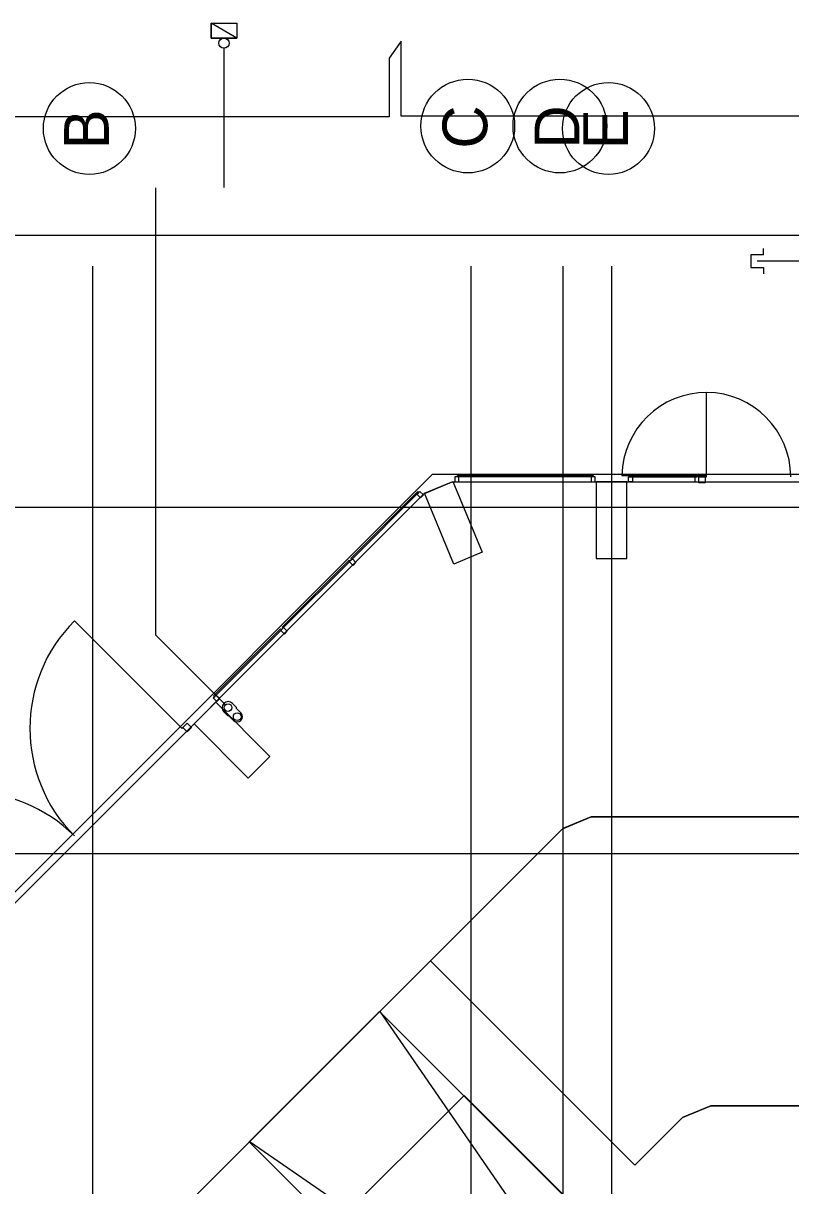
# Model space of a CAD drawing. Extents: x -264222 to -263592, y -1242345 to -1242048.
# Drawn here: x -263902.97 to -263887.96, y -1242101.22 to -1242078.49 of the extents above; entities that cross this region are included whole.
import ezdxf

# ---------------------------------------------------------------- set-up
doc = ezdxf.new("R2010")
doc.units = 0
for name, color, linetype in [('HESCON_OSI_STAVBY_KFA', 7, 'Continuous'), ('KFA_2D_SITUACIA_DSP', 7, 'Continuous'), ('KFA_SO_62-1_VO_TRASA_KABLOV_PROJEKT', 7, 'Continuous')]:
    doc.layers.add(name, color=color, linetype=linetype)

msp = doc.modelspace()

# ---------------------------------------------------------------- linework, layer by layer
at = {"layer": 'HESCON_OSI_STAVBY_KFA'}
for p, q in [((-263901.618, -1242083.237), (-263901.618, -1242083.237)), ((-263901.618, -1242083.237), (-263901.618, -1242246.707)), ((-263894.218, -1242083.237), (-263894.218, -1242083.237)), ((-263894.218, -1242083.237), (-263894.218, -1242246.707)), ((-263892.418, -1242083.237), (-263892.418, -1242083.237)), ((-263892.418, -1242083.237), (-263892.418, -1242246.707)), ((-263891.468, -1242083.237), (-263891.468, -1242083.237)), ((-263891.468, -1242083.237), (-263891.468, -1242246.707)), ((-263792.653, -1242087.957), (-263911.523, -1242087.957)), ((-263792.653, -1242094.732), (-263911.523, -1242094.732))]:
    msp.add_line(p, q, dxfattribs=at)
for centre, radius in [((-263901.678, -1242080.545), 0.899), ((-263894.278, -1242080.498), 0.916), ((-263892.478, -1242080.498), 0.916), ((-263891.528, -1242080.545), 0.899)]:
    msp.add_circle(centre, radius, dxfattribs=at)
at = {"layer": 'KFA_2D_SITUACIA_DSP'}
for p, q in [((-263899.296, -1242078.777), (-263899.296, -1242078.487)), ((-263899.296, -1242078.487), (-263898.796, -1242078.487)), ((-263898.796, -1242078.777), (-263899.296, -1242078.487)), ((-263898.796, -1242078.777), (-263899.296, -1242078.487)), ((-263899.296, -1242078.487), (-263899.296, -1242078.777)), ((-263898.796, -1242078.487), (-263898.796, -1242078.777)), ((-263898.796, -1242078.777), (-263899.296, -1242078.777)), ((-263899.296, -1242078.777), (-263898.796, -1242078.777)), ((-263899.046, -1242078.977), (-263899.047, -1242081.696)), ((-263900.379, -1242090.456), (-263900.379, -1242081.705)), ((-263788.143, -1242082.64), (-263924.143, -1242082.64)), ((-263888.493, -1242083.015), (-263888.743, -1242083.015)), ((-263888.743, -1242083.015), (-263888.743, -1242083.265)), ((-263888.493, -1242083.015), (-263888.493, -1242082.89)), ((-263888.743, -1242083.265), (-263888.493, -1242083.265)), ((-263886.743, -1242083.14), (-263888.618, -1242083.14)), ((-263888.493, -1242083.265), (-263888.493, -1242083.39)), ((-263889.613, -1242087.357), (-263889.613, -1242085.707)), ((-263894.491, -1242087.357), (-263894.531, -1242087.357)), ((-263894.531, -1242087.357), (-263894.531, -1242087.457)), ((-263894.451, -1242087.357), (-263894.491, -1242087.357)), ((-263894.478, -1242087.332), (-263891.828, -1242087.332)), ((-263894.478, -1242087.357), (-263894.478, -1242087.332)), ((-263891.828, -1242087.357), (-263894.478, -1242087.357)), ((-263894.451, -1242087.457), (-263894.451, -1242087.357)), ((-263891.828, -1242087.357), (-263891.868, -1242087.357)), ((-263891.868, -1242087.357), (-263891.868, -1242087.457)), ((-263891.828, -1242087.332), (-263891.828, -1242087.357)), ((-263891.788, -1242087.357), (-263891.828, -1242087.357)), ((-263891.788, -1242087.457), (-263891.788, -1242087.357)), ((-263891.263, -1242087.332), (-263889.613, -1242087.332)), ((-263891.138, -1242087.457), (-263891.138, -1242087.357)), ((-263891.138, -1242087.357), (-263891.098, -1242087.357)), ((-263889.798, -1242087.332), (-263891.098, -1242087.332)), ((-263891.098, -1242087.332), (-263891.098, -1242087.357)), ((-263891.098, -1242087.357), (-263889.798, -1242087.357)), ((-263891.098, -1242087.357), (-263891.058, -1242087.357)), ((-263891.058, -1242087.357), (-263891.058, -1242087.457)), ((-263889.798, -1242087.357), (-263889.838, -1242087.357)), ((-263889.838, -1242087.357), (-263889.838, -1242087.457)), ((-263889.798, -1242087.357), (-263889.798, -1242087.332)), ((-263889.758, -1242087.357), (-263889.798, -1242087.357)), ((-263889.758, -1242087.457), (-263889.758, -1242087.357)), ((-263889.758, -1242087.477), (-263889.758, -1242087.357)), ((-263889.758, -1242087.357), (-263889.638, -1242087.357)), ((-263889.638, -1242087.357), (-263889.613, -1242087.357)), ((-263889.638, -1242087.357), (-263889.638, -1242087.477)), ((-263895.258, -1242087.647), (-263896.566, -1242088.955)), ((-263895.24, -1242087.665), (-263895.258, -1242087.647)), ((-263895.245, -1242087.67), (-263895.216, -1242087.641)), ((-263895.216, -1242087.641), (-263895.146, -1242087.712)), ((-263895.135, -1242087.687), (-263894.581, -1242087.457)), ((-263895.125, -1242087.676), (-263894.571, -1242087.447)), ((-263894.581, -1242087.457), (-263809.355, -1242087.457)), ((-263894.571, -1242087.447), (-263893.997, -1242088.832)), ((-263894.531, -1242087.457), (-263894.451, -1242087.457)), ((-263891.868, -1242087.457), (-263891.788, -1242087.457)), ((-263891.168, -1242087.452), (-263891.768, -1242087.452)), ((-263891.768, -1242087.452), (-263891.768, -1242088.952)), ((-263891.168, -1242088.952), (-263891.168, -1242087.452)), ((-263891.058, -1242087.457), (-263891.138, -1242087.457)), ((-263889.838, -1242087.457), (-263889.758, -1242087.457)), ((-263889.638, -1242087.477), (-263889.758, -1242087.477)), ((-263908.663, -1242101.215), (-263895.135, -1242087.687)), ((-263896.548, -1242088.973), (-263895.24, -1242087.665)), ((-263895.273, -1242087.698), (-263895.245, -1242087.67)), ((-263895.202, -1242087.769), (-263895.273, -1242087.698)), ((-263895.146, -1242087.712), (-263895.202, -1242087.769)), ((-263894.551, -1242089.062), (-263895.125, -1242087.676)), ((-263897.906, -1242090.295), (-263896.598, -1242088.987)), ((-263896.58, -1242089.005), (-263897.888, -1242090.313)), ((-263896.598, -1242088.987), (-263896.58, -1242089.005)), ((-263896.592, -1242089.017), (-263896.564, -1242088.989)), ((-263896.566, -1242088.955), (-263896.548, -1242088.973)), ((-263896.564, -1242088.989), (-263896.536, -1242088.96)), ((-263896.536, -1242088.96), (-263896.465, -1242089.031)), ((-263893.997, -1242088.832), (-263894.551, -1242089.062)), ((-263891.768, -1242088.952), (-263891.168, -1242088.952)), ((-263896.522, -1242089.088), (-263896.592, -1242089.017)), ((-263896.465, -1242089.031), (-263896.522, -1242089.088)), ((-263899.866, -1242092.276), (-263901.97, -1242090.173)), ((-263899.25, -1242091.639), (-263897.942, -1242090.331)), ((-263897.924, -1242090.349), (-263899.232, -1242091.657)), ((-263897.942, -1242090.331), (-263897.924, -1242090.349)), ((-263897.936, -1242090.361), (-263897.908, -1242090.333)), ((-263897.865, -1242090.432), (-263897.936, -1242090.361)), ((-263897.908, -1242090.333), (-263897.88, -1242090.304)), ((-263897.888, -1242090.313), (-263897.906, -1242090.295)), ((-263897.88, -1242090.304), (-263897.809, -1242090.375)), ((-263897.809, -1242090.375), (-263897.865, -1242090.432)), ((-263899.018, -1242091.817), (-263900.379, -1242090.456)), ((-263899.255, -1242091.68), (-263899.227, -1242091.652)), ((-263899.185, -1242091.751), (-263899.255, -1242091.68)), ((-263899.232, -1242091.657), (-263899.25, -1242091.639)), ((-263899.227, -1242091.652), (-263899.199, -1242091.624)), ((-263899.199, -1242091.624), (-263899.128, -1242091.694)), ((-263899.128, -1242091.694), (-263899.185, -1242091.751)), ((-263899.207, -1242091.764), (-263899.631, -1242092.188)), ((-263898.147, -1242092.824), (-263899.207, -1242091.764)), ((-263898.969, -1242092.031), (-263899.047, -1242091.953)), ((-263899.047, -1242091.953), (-263898.969, -1242092.031)), ((-263898.804, -1242091.866), (-263898.882, -1242091.787)), ((-263898.804, -1242091.885), (-263898.804, -1242091.866)), ((-263898.715, -1242091.974), (-263898.804, -1242091.885)), ((-263899.764, -1242092.174), (-263899.849, -1242092.259)), ((-263899.679, -1242092.259), (-263899.764, -1242092.174)), ((-263899.631, -1242092.188), (-263898.571, -1242093.249)), ((-263898.949, -1242092.031), (-263898.969, -1242092.031)), ((-263898.861, -1242092.119), (-263898.949, -1242092.031)), ((-263899.849, -1242092.259), (-263899.866, -1242092.276)), ((-263899.849, -1242092.259), (-263899.764, -1242092.344)), ((-263899.764, -1242092.344), (-263899.679, -1242092.259)), ((-263898.571, -1242093.249), (-263898.147, -1242092.824)), ((-263891.868, -1242094.007), (-263892.422, -1242094.237)), ((-263874.98, -1242094.007), (-263891.868, -1242094.007)), ((-263892.422, -1242094.237), (-263895.005, -1242096.82)), ((-263895.005, -1242096.82), (-263891.01, -1242100.815)), ((-263890.082, -1242099.887), (-263889.528, -1242099.657)), ((-263889.528, -1242099.657), (-263874.98, -1242099.657)), ((-263891.01, -1242100.815), (-263890.082, -1242099.887))]:
    msp.add_line(p, q, dxfattribs=at)
for points in [[(-263794.893, -1242227.382), (-263808.968, -1242241.457), (-263894.968, -1242241.457), (-263909.043, -1242227.382), (-263909.043, -1242196.333), (-263914.143, -1242196.333), (-263914.143, -1242132.433), (-263909.043, -1242132.433), (-263909.043, -1242101.382), (-263894.968, -1242087.307), (-263808.968, -1242087.307), (-263794.893, -1242101.382), (-263794.893, -1242227.382)], [(-263909.043, -1242125.432), (-263902.343, -1242125.432), (-263902.343, -1242104.482), (-263902.112, -1242103.927), (-263898.54, -1242100.355), (-263895.995, -1242097.81), (-263892.423, -1242094.238), (-263891.868, -1242094.007), (-263812.071, -1242094.007), (-263811.513, -1242094.238), (-263801.823, -1242103.927), (-263801.593, -1242104.482), (-263801.593, -1242224.282), (-263801.824, -1242224.838), (-263805.392, -1242228.407)], [(-263891.681, -1242108.095), (-263894.08, -1242107.101), (-263892.944, -1242105.964), (-263898.552, -1242100.364), (-263896.003, -1242097.814), (-263890.399, -1242103.418), (-263889.262, -1242102.282), (-263888.268, -1242104.681), (-263891.681, -1242108.095)], [(-263898.54, -1242100.355), (-263895.995, -1242097.81), (-263890.341, -1242106.025), (-263898.533, -1242100.366)], [(-263892.018, -1242220.33), (-263892.018, -1242181.432), (-263893.618, -1242181.432), (-263893.618, -1242147.332), (-263892.018, -1242147.332), (-263892.018, -1242108.434), (-263891.673, -1242108.09), (-263894.073, -1242107.096), (-263892.937, -1242105.959), (-263896.896, -1242101.999), (-263894.351, -1242099.454), (-263890.391, -1242103.413), (-263889.254, -1242102.277), (-263888.26, -1242104.677), (-263887.916, -1242104.332), (-263816.02, -1242104.332)]]:
    msp.add_lwpolyline(points, dxfattribs=at)
msp.add_lwpolyline([(-263891.01, -1242100.815), (-263895.005, -1242096.82), (-263892.422, -1242094.237), (-263891.868, -1242094.007), (-263874.98, -1242094.007), (-263874.98, -1242099.657), (-263889.528, -1242099.657), (-263890.082, -1242099.887)], close=True, dxfattribs=at)
for centre, radius in [((-263899.046, -1242078.877), 0.1), ((-263898.965, -1242091.87), 0.075), ((-263898.788, -1242092.047), 0.075)]:
    msp.add_circle(centre, radius, dxfattribs=at)
for centre, radius, start, end in [((-263889.613, -1242087.357), 1.65, 0, 179.1318), ((-263899.866, -1242092.276), 2.975, 135.0001, 225.0001), ((-263898.965, -1242091.87), 0.117, 45, 225), ((-263898.788, -1242092.047), 0.103, 225, 45), ((-263904.074, -1242096.484), 2.975, 44.9999, 134.9999)]:
    msp.add_arc(centre, radius, start, end, dxfattribs=at)
at = {"layer": 'KFA_SO_62-1_VO_TRASA_KABLOV_PROJEKT'}
for p, q in [((-263895.58, -1242078.835), (-263895.815, -1242079.173)), ((-263895.58, -1242080.304), (-263895.58, -1242078.835)), ((-263895.815, -1242079.173), (-263895.815, -1242080.314)), ((-263895.815, -1242080.314), (-263915.1, -1242080.314)), ((-263876.274, -1242080.304), (-263895.58, -1242080.304))]:
    msp.add_line(p, q, dxfattribs=at)

# ---------------------------------------------------------------- texts
at = {"layer": 'HESCON_OSI_STAVBY_KFA'}
for s, p in [('C', (-263893.897, -1242080.939)), ('B', (-263901.297, -1242080.952)), ('D', (-263892.097, -1242080.939)), ('E', (-263891.147, -1242080.952))]:
    msp.add_text(s, height=0.875, rotation=90, dxfattribs=at).set_placement(p)

doc.saveas('drawing.dxf')
